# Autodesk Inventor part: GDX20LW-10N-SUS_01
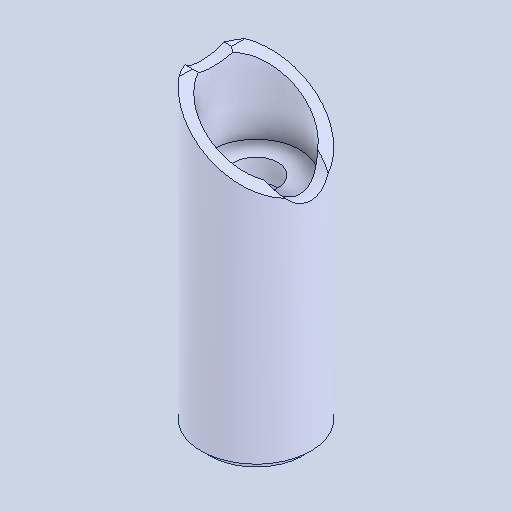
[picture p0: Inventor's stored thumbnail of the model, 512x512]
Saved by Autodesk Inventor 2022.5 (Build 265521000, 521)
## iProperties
Created: 2024-06
Part Number: GDX20LW-10N-SUS_01
Material: 一般
Document SubType Name: Modeling
Designer: ImaoCorp
Density: 1 g/cm^3
Appearance: 既定
Author: ImaoCorp
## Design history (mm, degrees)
feature "GDX20LW-10N-SUS_01"
node "ソリッド1"
